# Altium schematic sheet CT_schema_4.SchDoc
size 151 x 163 mm
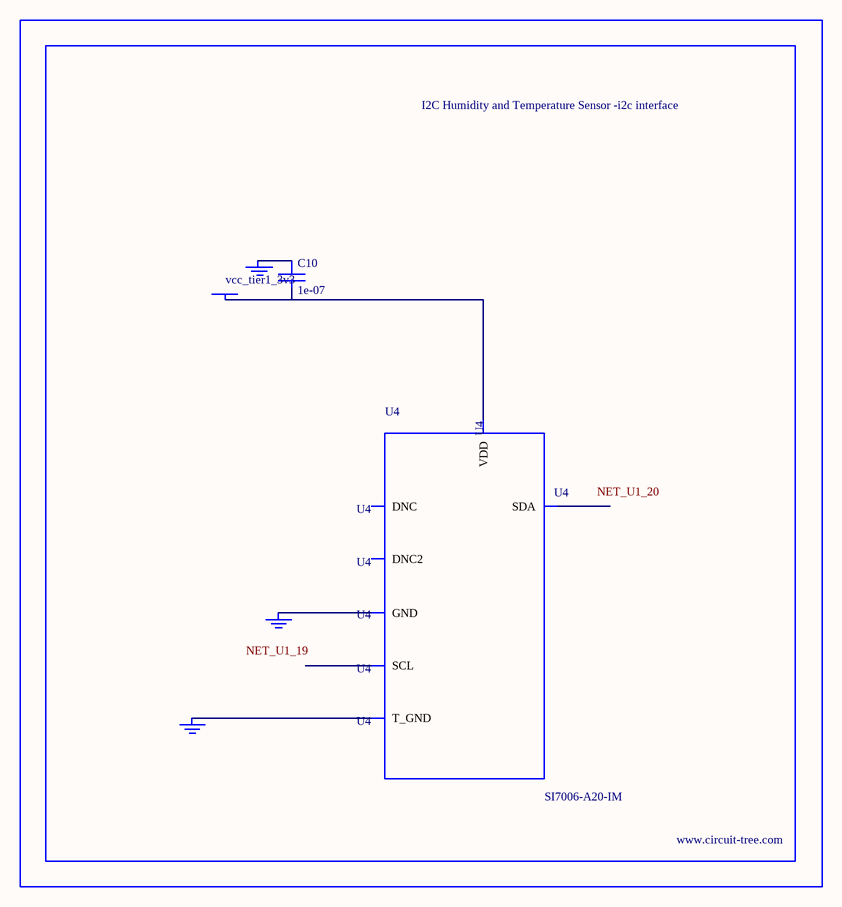
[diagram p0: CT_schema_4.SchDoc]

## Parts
BORDER3  (no value)
C10  1e-07  [C0402]
GND_INSTANCE_3_0  (no value)
GND_INSTANCE_3_1  (no value)
GND_INSTANCE_3_2  (no value)
POWER_INSTANCE_3_0  vcc_tier1_3v3
U4  SI7006-A20-IM  [DFN-6]

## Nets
NetC10_1: C10.1 GND_INSTANCE_3_0.0(GND)
NetC10_2: C10.2 POWER_INSTANCE_3_0.0(PWR) U4.5(VDD)
NetGND_INSTANCE_3_1_0: GND_INSTANCE_3_1.0(GND) U4.7(T_GND)
NetGND_INSTANCE_3_2_0: GND_INSTANCE_3_2.0(GND) U4.2(GND)

Not connected (* = marked no-connect by the designer): U4 1(SDA) 3(DNC) 4(DNC2) 6(SCL)

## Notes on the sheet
- Labels drawn without touching a wire or pin: NET_U1_19, NET_U1_20

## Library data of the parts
BORDER3 = BORDER_PAGE3
C10 = C0402C104K3RACTU
GND_INSTANCE_3_0-GND_INSTANCE_3_2 = GND
POWER_INSTANCE_3_0 = PWR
